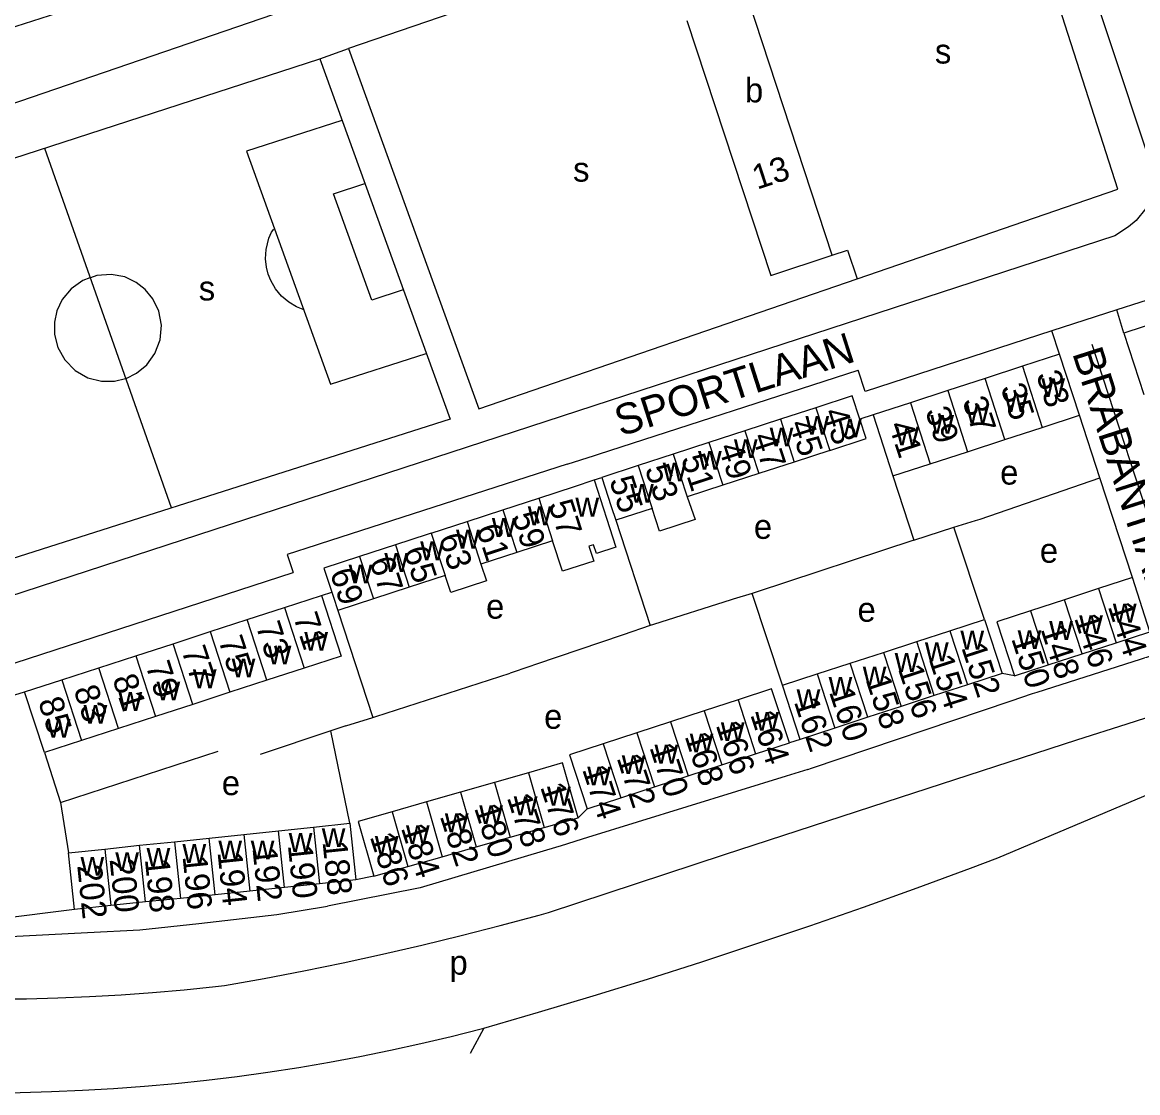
# Model space of a CAD drawing. Extents: x 157569 to 159501, y 382907 to 384670.
# Drawn here: x 159211.5 to 159393.6, y 382908.9 to 383083.6 of the extents above; entities that cross this region are included whole.
import ezdxf

# ---------------------------------------------------------------- set-up
doc = ezdxf.new("R2010")
doc.units = 0
for name, color, linetype in [('BLT_Basislijn', 7, 'Continuous'), ('BLT_Bebouwing', 7, 'Continuous'), ('BLT_Centroide', 7, 'Continuous'), ('BLT_Huisnummer', 7, 'Continuous'), ('BLT_Huisnummer_ tussenligend', 7, 'Continuous'), ('BLT_Onderverdeling_panden', 7, 'Continuous'), ('BLT_Straatnaam', 7, 'Continuous'), ('BLT_Vlakafsluiter', 7, 'Continuous')]:
    doc.layers.add(name, color=color, linetype=linetype)

msp = doc.modelspace()

# ---------------------------------------------------------------- linework, layer by layer
at = {"layer": 'BLT_Basislijn'}
for p, q in [((159260.08, 383077.63), (159264.78, 383079.33)), ((159215.14, 383063.07), (159235.82, 383004.38)), ((159401.11, 383040.19), (159390.17, 383036.65)), ((159390.17, 383036.65), (159379.54, 383033.22)), ((159391.3, 383032.88), (159390.17, 383036.65)), ((159379.54, 383033.22), (159349.09, 383023.36)), ((159380.82, 383029.43), (159379.54, 383033.22)), ((159386.07, 383031.08), (159400.03, 382988.25)), ((159349.09, 383023.36), (159347.93, 383026.82)), ((159350.38, 383019.52), (159348.22, 383018.81)), ((159387.4, 383009.25), (159384.08, 383019.46)), ((159300.47, 383011.47), (159304.93, 383012.91)), ((159304.85, 383008.9), (159306.11, 383009.3)), ((159353.62, 383009.55), (159357.04, 382999.04)), ((159392.7, 382992.96), (159387.4, 383009.25)), ((159308.38, 383002.33), (159314.02, 382985.14)), ((159363.53, 383001.17), (159367.11, 383002.29)), ((159368.56, 382986.12), (159363.53, 383001.17)), ((159259.5, 382998.26), (159254.76, 382996.74)), ((159254.76, 382996.74), (159255.72, 382993.79)), ((159210.34, 382979.03), (159255.72, 382993.79)), ((159260.34, 382990.04), (159262.03, 382990.59)), ((159335.57, 382975.37), (159330.64, 382990.35)), ((159263.01, 382987.57), (159268.71, 382970.09)), ((159314.02, 382985.14), (159309.57, 382983.62)), ((159294.37, 382978.44), (159291.12, 382977.33)), ((159373.44, 382976.89), (159371.44, 382977.29)), ((159203.61, 382971.77), (159211.89, 382974.28)), ((159372.92, 382972.81), (159376.38, 382974.01)), ((159264.33, 382968.73), (159268.71, 382970.09)), ((159261.89, 382967.91), (159250.34, 382964.05)), ((159264.33, 382968.73), (159261.89, 382967.91)), ((159264.96, 382952.85), (159261.89, 382967.91)), ((159338.45, 382966.54), (159336.71, 382965.97)), ((159215.12, 382964.38), (159217.75, 382956.24)), ((159217.75, 382956.24), (159243.49, 382964.6)), ((159339.74, 382961.64), (159336.21, 382960.53)), ((159217.75, 382956.24), (159219.08, 382948.01)), ((159302.25, 382953.75), (159303.72, 382955.19)), ((159268.91, 382944.2), (159265.93, 382943.61)), ((159220.06, 382938.76), (159207.21, 382937.18))]:
    msp.add_line(p, q, dxfattribs=at)
for points in [[(159181.14, 383122.58), (159195.5, 383078.21), (159225.49, 383087.86)], [(159377.3, 383117.67), (159381.19, 383104.13), (159395.86, 383059.85), (159395.9, 383056.38), (159394.91, 383053.22), (159393.32, 383051.25), (159392.07, 383050.23), (159389.81, 383048.77), (159167.86, 382976.29)], [(159347.8, 383041.73), (159390.34, 383056.35), (159371.25, 383115.93)], [(159315.54, 383096.78), (159264.78, 383079.33)], [(159274.13, 383092.35), (159167.67, 383055.85)], [(159264.78, 383079.33), (159286.05, 383020.51)], [(159260.08, 383077.63), (159281.35, 383018.81), (159191.16, 382990.1), (159170.19, 383048.51)], [(159170.19, 383048.51), (159260.08, 383077.63)], [(159263.66, 383067.6), (159248.1, 383062.56), (159261.81, 383024.52), (159277.43, 383029.57)], [(159273.69, 383039.93), (159268.56, 383038.24), (159262.3, 383055.61), (159267.4, 383057.28)], [(159257.36, 383036.74), (159256.27, 383037.16), (159255, 383037.91), (159253.8, 383038.92), (159252.87, 383040.08), (159252.08, 383041.45), (159251.65, 383042.48), (159251.36, 383043.64), (159251.23, 383044.99), (159251.33, 383046.5), (159251.78, 383048.37), (159252.18, 383049.34), (159252.58, 383049.87)], [(159343.71, 383045.59), (159346.18, 383046.44), (159347.8, 383041.73)], [(159222.56, 383041.9), (159221.4, 383041.48), (159219.47, 383040.1), (159218.05, 383038.37), (159217.17, 383036.5), (159216.77, 383034.66), (159216.78, 383032.67), (159217.32, 383030.54), (159218.45, 383028.5), (159220.14, 383026.78), (159222.22, 383025.59), (159224.45, 383025.03), (159226.57, 383025.03), (159228.37, 383025.47)], [(159228.45, 383025.48), (159230.18, 383026.33), (159231.82, 383027.68), (159233.17, 383029.54), (159234.02, 383031.78), (159234.23, 383034.18), (159233.79, 383036.48), (159232.85, 383038.46), (159231.59, 383040), (159230.11, 383041.16), (159228.24, 383042.04), (159226.04, 383042.47), (159223.67, 383042.3), (159222.63, 383041.92)], [(159286.05, 383020.51), (159347.8, 383041.73)], [(159304.93, 383012.91), (159305.58, 383013.11), (159347.93, 383026.82)], [(159228.4, 383025.47), (159228.45, 383025.48)], [(159300.47, 383011.47), (159260.12, 382998.46), (159259.5, 382998.26)], [(159367.11, 383002.29), (159367.85, 383002.52), (159387.4, 383009.25)], [(159357.04, 382999.04), (159363.53, 383001.17)], [(159357.04, 382999.04), (159331.29, 382990.55), (159330.64, 382990.35)], [(159330.64, 382990.35), (159327.52, 382989.41), (159327.22, 382989.32)], [(159327.22, 382989.32), (159314.52, 382985.31), (159314.02, 382985.14)], [(159309.57, 382983.62), (159295.28, 382978.76), (159294.37, 382978.44)], [(159376.38, 382974.01), (159377.15, 382974.27), (159396.73, 382980.51)], [(159268.71, 382970.09), (159269.23, 382970.25), (159291.12, 382977.33)], [(159297.41, 382938.27), (159326.12, 382947.74), (159354.86, 382957.13), (159383.63, 382966.44), (159391.84, 382969.08), (159421.78, 382978.69)], [(159339.74, 382961.64), (159340.35, 382961.83), (159372.92, 382972.81)], [(159370.75, 382947.19), (159424.71, 382970.03)], [(159336.21, 382960.53), (159303.75, 382950.51), (159302.89, 382950.24)], [(159302.89, 382950.24), (159299.29, 382949.12), (159299.07, 382949.05)], [(159299.07, 382949.05), (159276.46, 382942.28), (159261.34, 382939.31)], [(159286.87, 382919.38), (159295.79, 382921.98), (159304.68, 382924.65), (159313.56, 382927.4), (159322.4, 382930.23), (159331.23, 382933.13), (159340.03, 382936.11), (159348.8, 382939.17), (159357.55, 382942.3), (159366.26, 382945.51), (159370.75, 382947.19)], [(159222.16, 382935), (159230.71, 382935.43), (159240.33, 382936.49), (159253.08, 382937.94), (159261.34, 382939.31)], [(159244.51, 382926.34), (159250.98, 382927.5), (159257.45, 382928.75), (159263.89, 382930.07), (159270.32, 382931.47), (159276.74, 382932.94), (159283.13, 382934.5), (159289.5, 382936.13), (159295.86, 382937.84), (159297.41, 382938.27)], [(159193.08, 382934.78), (159208.48, 382934.32), (159222.16, 382935)], [(159186.43, 382924.75), (159191.58, 382924.48), (159196.73, 382924.29), (159201.88, 382924.18), (159207.04, 382924.15), (159212.19, 382924.2), (159217.34, 382924.33), (159222.49, 382924.54), (159227.64, 382924.83), (159232.78, 382925.2), (159237.92, 382925.65), (159243.05, 382926.17), (159244.51, 382926.34)], [(159185.83, 382909.43), (159190.9, 382909.17), (159195.97, 382908.98), (159201.04, 382908.88), (159206.12, 382908.85), (159211.19, 382908.9), (159216.26, 382909.04), (159221.33, 382909.25), (159226.4, 382909.55), (159231.46, 382909.92), (159236.51, 382910.37), (159241.56, 382910.91), (159246.6, 382911.52), (159251.62, 382912.21), (159256.64, 382912.98), (159261.64, 382913.83), (159266.63, 382914.76), (159271.6, 382915.77), (159276.56, 382916.86), (159281.5, 382918.02), (159286.42, 382919.26), (159286.87, 382919.38)]]:
    msp.add_lwpolyline(points, dxfattribs=at)
at = {"layer": 'BLT_Bebouwing'}
for p, q in [((159343.71, 383045.59), (159330.06, 383087.23)), ((159397.44, 383034.89), (159391.3, 383032.88)), ((159391.3, 383032.88), (159394.54, 383022.87)), ((159380.82, 383029.43), (159374.74, 383027.45)), ((159384.08, 383019.46), (159380.82, 383029.43)), ((159374.74, 383027.45), (159368.65, 383025.47)), ((159368.65, 383025.47), (159362.56, 383023.48)), ((159362.56, 383023.48), (159356.46, 383021.5)), ((159341.04, 383020.69), (159335.29, 383018.82)), ((159356.46, 383021.5), (159350.38, 383019.52)), ((159335.29, 383018.82), (159329.44, 383016.91)), ((159350.38, 383019.52), (159353.62, 383009.55)), ((159377.99, 383017.48), (159384.08, 383019.46)), ((159371.89, 383015.5), (159377.99, 383017.48)), ((159329.44, 383016.91), (159323.59, 383015.01)), ((159365.8, 383013.51), (159371.89, 383015.5)), ((159323.59, 383015.01), (159317.74, 383013.1)), ((159343.32, 383013.72), (159337.52, 383011.82)), ((159359.71, 383011.53), (159365.8, 383013.51)), ((159317.74, 383013.1), (159312.04, 383011.24)), ((159337.52, 383011.82), (159331.71, 383009.93)), ((159312.04, 383011.24), (159306.11, 383009.3)), ((159331.71, 383009.93), (159325.87, 383008.03)), ((159353.62, 383009.55), (159359.71, 383011.53)), ((159304.85, 383008.9), (159308.37, 382997.93)), ((159325.87, 383008.03), (159320.02, 383006.12)), ((159295.8, 383005.93), (159301.65, 383007.84)), ((159289.96, 383004.03), (159295.8, 383005.93)), ((159284.11, 383002.13), (159289.96, 383004.03)), ((159278.26, 383000.22), (159284.11, 383002.13)), ((159298.07, 382998.98), (159292.22, 382997.07)), ((159299.69, 382993.99), (159298.07, 382998.98)), ((159272.41, 382998.32), (159266.57, 382996.41)), ((159292.22, 382997.07), (159286.37, 382995.17)), ((159266.57, 382996.41), (159260.75, 382994.51)), ((159260.75, 382994.51), (159262.03, 382990.59)), ((159280.52, 382993.27), (159274.67, 382991.37)), ((159392.7, 382992.96), (159387.15, 382991.15)), ((159395.57, 382984.1), (159392.7, 382992.96)), ((159254.29, 382988.07), (159260.34, 382990.04)), ((159274.67, 382991.37), (159268.82, 382989.47)), ((159387.15, 382991.15), (159381.62, 382989.35)), ((159248.23, 382986.1), (159254.29, 382988.07)), ((159268.82, 382989.47), (159263.01, 382987.57)), ((159381.62, 382989.35), (159376.09, 382987.55)), ((159242.17, 382984.13), (159248.23, 382986.1)), ((159362.91, 382984.28), (159368.56, 382986.12)), ((159368.56, 382986.12), (159371.44, 382977.29)), ((159357.49, 382982.51), (159362.91, 382984.28)), ((159236.12, 382982.16), (159242.17, 382984.13)), ((159352.07, 382980.75), (159357.49, 382982.51)), ((159390.04, 382982.3), (159395.57, 382984.1)), ((159230.06, 382980.19), (159236.12, 382982.16)), ((159346.65, 382978.98), (159352.07, 382980.75)), ((159384.5, 382980.5), (159390.04, 382982.3)), ((159224, 382978.22), (159230.06, 382980.19)), ((159341.23, 382977.22), (159346.65, 382978.98)), ((159378.97, 382978.69), (159384.5, 382980.5)), ((159217.95, 382976.25), (159224, 382978.22)), ((159257.51, 382978.17), (159251.45, 382976.2)), ((159335.57, 382975.37), (159341.23, 382977.22)), ((159371.44, 382977.29), (159365.78, 382975.45)), ((159373.44, 382976.89), (159378.97, 382978.69)), ((159211.89, 382974.28), (159217.95, 382976.25)), ((159251.45, 382976.2), (159245.39, 382974.23)), ((159338.45, 382966.54), (159335.57, 382975.37)), ((159365.78, 382975.45), (159360.37, 382973.68)), ((159215.12, 382964.38), (159211.89, 382974.28)), ((159245.39, 382974.23), (159239.34, 382972.26)), ((159360.37, 382973.68), (159354.95, 382971.92)), ((159239.34, 382972.26), (159233.28, 382970.29)), ((159328.33, 382973.01), (159322.83, 382971.21)), ((159354.95, 382971.92), (159349.53, 382970.15)), ((159233.28, 382970.29), (159227.22, 382968.31)), ((159322.83, 382971.21), (159317.33, 382969.42)), ((159349.53, 382970.15), (159344.11, 382968.38)), ((159227.22, 382968.31), (159221.17, 382966.34)), ((159317.33, 382969.42), (159311.83, 382967.62)), ((159344.11, 382968.38), (159338.45, 382966.54)), ((159221.17, 382966.34), (159215.12, 382964.38)), ((159311.83, 382967.62), (159306.33, 382965.83)), ((159331.21, 382964.17), (159336.71, 382965.97)), ((159325.71, 382962.38), (159331.21, 382964.17)), ((159294.15, 382961.1), (159288.59, 382959.51)), ((159314.71, 382958.79), (159320.21, 382960.58)), ((159320.21, 382960.58), (159325.71, 382962.38)), ((159288.59, 382959.51), (159283.03, 382957.92)), ((159309.21, 382956.99), (159314.71, 382958.79)), ((159283.03, 382957.92), (159277.47, 382956.32)), ((159303.72, 382955.19), (159309.21, 382956.99)), ((159277.47, 382956.32), (159271.91, 382954.73)), ((159296.72, 382952.16), (159302.25, 382953.75)), ((159247.69, 382951.03), (159253.36, 382951.63)), ((159253.36, 382951.63), (159259.03, 382952.23)), ((159259.03, 382952.23), (159264.96, 382952.85)), ((159264.96, 382952.85), (159265.93, 382943.61)), ((159291.16, 382950.57), (159296.72, 382952.16)), ((159230.67, 382949.24), (159236.35, 382949.83)), ((159236.35, 382949.83), (159242.02, 382950.43)), ((159242.02, 382950.43), (159247.69, 382951.03)), ((159285.6, 382948.98), (159291.16, 382950.57)), ((159219.08, 382948.01), (159225, 382948.64)), ((159220.06, 382938.76), (159219.08, 382948.01)), ((159225, 382948.64), (159230.67, 382949.24)), ((159280.03, 382947.38), (159285.6, 382948.98)), ((159274.47, 382945.79), (159280.03, 382947.38)), ((159268.91, 382944.2), (159274.47, 382945.79)), ((159254.34, 382942.38), (159248.67, 382941.78)), ((159260.01, 382942.98), (159254.34, 382942.38)), ((159265.93, 382943.61), (159260.01, 382942.98)), ((159237.32, 382940.58), (159231.65, 382939.99)), ((159242.99, 382941.18), (159237.32, 382940.58)), ((159248.67, 382941.78), (159242.99, 382941.18)), ((159225.98, 382939.39), (159220.06, 382938.76)), ((159231.65, 382939.99), (159225.98, 382939.39))]:
    msp.add_line(p, q, dxfattribs=at)
for points in [[(159319.96, 383083.92), (159333.69, 383042.3), (159343.71, 383045.59)], [(159348.22, 383018.81), (159346.98, 383022.63), (159341.04, 383020.69)], [(159343.32, 383013.72), (159349.26, 383015.65), (159348.22, 383018.81)], [(159301.65, 383007.84), (159304.85, 383008.9)], [(159306.11, 383009.3), (159307.65, 383004.55), (159308.38, 383002.33)], [(159320.02, 383006.12), (159321.33, 383002.42), (159315.53, 383000.53), (159314.32, 383004.26)], [(159314.32, 383004.26), (159308.38, 383002.33)], [(159278.26, 383000.22), (159277.58, 383000), (159272.41, 382998.32)], [(159305.21, 382996.9), (159304.75, 382998.32), (159304.01, 382998.08), (159304.8, 382995.66), (159299.69, 382993.99)], [(159308.37, 382997.93), (159305.21, 382996.9)], [(159286.37, 382995.17), (159287.26, 382992.42), (159281.46, 382990.53), (159280.52, 382993.27)], [(159260.34, 382990.04), (159263.56, 382980.14), (159257.51, 382978.17)], [(159262.03, 382990.59), (159262.3, 382989.75), (159263.01, 382987.57)], [(159376.09, 382987.55), (159370.55, 382985.74), (159373.44, 382976.89)], [(159336.71, 382965.97), (159333.82, 382974.8), (159328.33, 382973.01)], [(159306.33, 382965.83), (159300.83, 382964.03), (159303.72, 382955.19)], [(159302.25, 382953.75), (159299.71, 382962.7), (159294.15, 382961.1)], [(159271.91, 382954.73), (159266.35, 382953.13), (159268.91, 382944.2)]]:
    msp.add_lwpolyline(points, dxfattribs=at)
at = {"layer": 'BLT_Onderverdeling_panden'}
for p, q in [((159374.74, 383027.45), (159377.99, 383017.48)), ((159371.89, 383015.5), (159368.65, 383025.47)), ((159362.56, 383023.48), (159365.8, 383013.51)), ((159341.04, 383020.69), (159343.32, 383013.72)), ((159356.46, 383021.5), (159359.71, 383011.53)), ((159335.29, 383018.82), (159337.52, 383011.82)), ((159329.44, 383016.91), (159331.71, 383009.93)), ((159323.59, 383015.01), (159325.87, 383008.03)), ((159317.74, 383013.1), (159320.02, 383006.12)), ((159312.04, 383011.24), (159314.32, 383004.26)), ((159295.8, 383005.93), (159298.07, 382998.98)), ((159289.96, 383004.03), (159292.22, 382997.07)), ((159284.11, 383002.13), (159286.37, 382995.17)), ((159278.26, 383000.22), (159280.52, 382993.27)), ((159272.41, 382998.32), (159274.67, 382991.37)), ((159266.57, 382996.41), (159268.82, 382989.47)), ((159387.15, 382991.15), (159390.04, 382982.3)), ((159254.29, 382988.07), (159257.51, 382978.17)), ((159384.5, 382980.5), (159381.62, 382989.35)), ((159251.45, 382976.2), (159248.23, 382986.1)), ((159376.09, 382987.55), (159378.97, 382978.69)), ((159362.91, 382984.28), (159365.78, 382975.45)), ((159242.17, 382984.13), (159245.39, 382974.23)), ((159360.37, 382973.68), (159357.49, 382982.51)), ((159239.34, 382972.26), (159236.12, 382982.16)), ((159352.07, 382980.75), (159354.95, 382971.92)), ((159230.06, 382980.19), (159233.28, 382970.29)), ((159349.53, 382970.15), (159346.65, 382978.98)), ((159227.22, 382968.31), (159224, 382978.22)), ((159341.23, 382977.22), (159344.11, 382968.38)), ((159217.95, 382976.25), (159221.17, 382966.34)), ((159328.33, 382973.01), (159331.21, 382964.17)), ((159322.83, 382971.21), (159325.71, 382962.38)), ((159317.33, 382969.42), (159320.21, 382960.58)), ((159311.83, 382967.62), (159314.71, 382958.79)), ((159306.33, 382965.83), (159309.21, 382956.99)), ((159294.15, 382961.1), (159296.72, 382952.16)), ((159288.59, 382959.51), (159291.16, 382950.57)), ((159283.03, 382957.92), (159285.6, 382948.98)), ((159277.47, 382956.32), (159280.03, 382947.38)), ((159271.91, 382954.73), (159274.47, 382945.79)), ((159254.34, 382942.38), (159253.36, 382951.63)), ((159259.03, 382952.23), (159260.01, 382942.98)), ((159236.35, 382949.83), (159237.32, 382940.58)), ((159242.99, 382941.18), (159242.02, 382950.43)), ((159247.69, 382951.03), (159248.67, 382941.78)), ((159225, 382948.64), (159225.98, 382939.39)), ((159231.65, 382939.99), (159230.67, 382949.24))]:
    msp.add_line(p, q, dxfattribs=at)
at = {"layer": 'BLT_Vlakafsluiter'}
msp.add_line((159286.87, 382919.38), (159284.62, 382915.23), dxfattribs=at)

# ---------------------------------------------------------------- texts
at = {"layer": 'BLT_Centroide'}
for s, p in [('s', (159360.47, 383076.89)), ('b', (159329.47, 383070.55)), ('s', (159301.42, 383057.61)), ('s', (159240.32, 383038.21)), ('w', (159377.84, 383022.43)), ('w', (159371.78, 383020.01)), ('w', (159365.48, 383018.19)), ('w', (159339.34, 383016.28)), ('w', (159344.67, 383015.83)), ('w', (159359.72, 383016.43)), ('w', (159333.5, 383014.38)), ('w', (159354.03, 383014.55)), ('w', (159327.66, 383012.47)), ('w', (159321.81, 383010.56)), ('w', (159316.03, 383008.67)), ('e', (159371.11, 383008.14)), ('w', (159310.73, 383005.19)), ('w', (159294.02, 383001.5)), ('w', (159301.79, 383002.91)), ('w', (159288.16, 382999.59)), ('w', (159282.31, 382997.69)), ('e', (159330.92, 382999.28)), ('w', (159276.47, 382995.78)), ('e', (159377.59, 382995.38)), ('w', (159270.62, 382993.89)), ('w', (159264.78, 382992)), ('e', (159287.21, 382986.25)), ('e', (159347.84, 382985.75)), ('w', (159389.52, 382985.6)), ('w', (159384.02, 382983.72)), ('w', (159364.63, 382981.21)), ('w', (159373.97, 382981.28)), ('w', (159379.12, 382982.79)), ('w', (159257.55, 382981)), ('w', (159251.57, 382978.77)), ('w', (159353.91, 382977.55)), ('w', (159358.84, 382979.29)), ('w', (159245.69, 382976.66)), ('w', (159239.36, 382974.9)), ('w', (159348.69, 382975.35)), ('w', (159233.43, 382972.9)), ('w', (159343.12, 382973.67)), ('w', (159227.22, 382971.19)), ('w', (159337.9, 382971.63)), ('w', (159221.52, 382969.08)), ('w', (159215.53, 382966.8)), ('e', (159296.68, 382968.27)), ('w', (159331.16, 382967.95)), ('w', (159325.53, 382966.25)), ('w', (159320.45, 382964.42)), ('w', (159314.71, 382962.6)), ('w', (159309.36, 382960.88)), ('w', (159303.73, 382959.01)), ('e', (159244.08, 382957.43)), ('w', (159297.17, 382955.73)), ('w', (159291.74, 382954.15)), ('w', (159286.1, 382952.7)), ('w', (159280.49, 382951.37)), ('w', (159260.39, 382948.97)), ('w', (159274.14, 382949.44)), ('w', (159243.52, 382946.94)), ('w', (159248.8, 382946.94)), ('w', (159255, 382948.16)), ('w', (159269.06, 382947.68)), ('w', (159226.7, 382945.03)), ('w', (159231.8, 382945.73)), ('w', (159237.66, 382946.36)), ('w', (159221.02, 382944.28)), ('p', (159281.24, 382928.12))]:
    msp.add_text(s, height=4, dxfattribs=at).set_placement(p)
at = {"layer": 'BLT_Huisnummer'}
for s, rotation, p in [('13', 18.0976, (159331.45, 383056.28)), ('33', 288.0431, (159376.96, 383026.07)), ('37', 288.0431, (159364.91, 383021.82)), ('43', 288.0572, (159342.19, 383019.99)), ('41', 288.0431, (159352.87, 383017.86)), ('47', 288.0572, (159330.62, 383015.98)), ('51', 288.0572, (159318.99, 383012.43)), ('55', 288.0581, (159307.29, 383008.84)), ('57', 288.0189, (159297.35, 383004.96)), ('61', 288.0161, (159285.53, 383001.02)), ('65', 288.0517, (159273.68, 382997.38)), ('69', 288.0517, (159261.69, 382993.8)), ('144', 288.0431, (159388.66, 382988.24)), ('71', 288.0431, (159255.72, 382986.53)), ('148', 288.0431, (159377.68, 382984.56)), ('75', 288.0431, (159243.48, 382982.74)), ('150', 288.0431, (159372.89, 382983.01)), ('152', 288.0431, (159364.75, 382981.56)), ('79', 288.0431, (159231.61, 382978.6)), ('156', 288.0431, (159354.42, 382978.06)), ('85', 288.0431, (159214.06, 382972.75)), ('160', 288.0431, (159343.16, 382974.3)), ('162', 288.0431, (159337.43, 382972.68)), ('164', 288.0431, (159330.3, 382970.59)), ('168', 288.0431, (159319.59, 382967.06)), ('172', 288.0431, (159308.5, 382963.51)), ('174', 288.0431, (159302.87, 382961.65)), ('176', 288.0431, (159296.01, 382958.79)), ('180', 288.0431, (159285.24, 382955.34)), ('184', 288.0431, (159273.28, 382952.08)), ('186', 288.0431, (159268.2, 382950.66)), ('192', 275.9431, (159249.08, 382948.76)), ('188', 275.9431, (159260.52, 382949.79)), ('200', 275.9431, (159225.76, 382946.95)), ('196', 275.9431, (159237.67, 382947.42)), ('202', 275.9431, (159220.48, 382945.93))]:
    msp.add_text(s, height=4, rotation=rotation, dxfattribs=at).set_placement(p)
at = {"layer": 'BLT_Huisnummer_ tussenligend'}
for s, rotation, p in [('35', 288.0431, (159371.16, 383023.98)), ('39', 288.0431, (159358.85, 383020.17)), ('45', 288.0572, (159336.65, 383018.08)), ('49', 288.0572, (159325.08, 383014.27)), ('53', 288.0572, (159313.1, 383010.73)), ('59', 288.0189, (159291.39, 383003.04)), ('63', 288.0161, (159279.43, 382999.53)), ('67', 288.0517, (159268.14, 382995.69)), ('146', 288.0431, (159383.16, 382986.36)), ('73', 288.0431, (159249.61, 382985.06)), ('77', 288.0431, (159237.45, 382981.08)), ('154', 288.0431, (159359.44, 382979.65)), ('81', 288.0431, (159226.19, 382976.48)), ('83', 288.0431, (159219.86, 382974.68)), ('158', 288.0431, (159349.12, 382976.34)), ('166', 288.0431, (159324.67, 382968.89)), ('170', 288.0431, (159313.85, 382965.24)), ('178', 288.0431, (159290.58, 382957.05)), ('182', 288.0431, (159279.63, 382953.99)), ('194', 275.9431, (159243.38, 382948.11)), ('190', 275.9431, (159254.86, 382949.24)), ('198', 275.9431, (159231.52, 382946.95))]:
    msp.add_text(s, height=4, rotation=rotation, dxfattribs=at).set_placement(p)
at = {"layer": 'BLT_Straatnaam'}
for s, rotation, p in [('SPORTLAAN', 17.7421, (159309.17, 383015.97)), ('BRABANTIAPAD', 287.7421, (159382.85, 383029.61))]:
    msp.add_text(s, height=5, rotation=rotation, dxfattribs=at).set_placement(p)

doc.saveas('drawing.dxf')
